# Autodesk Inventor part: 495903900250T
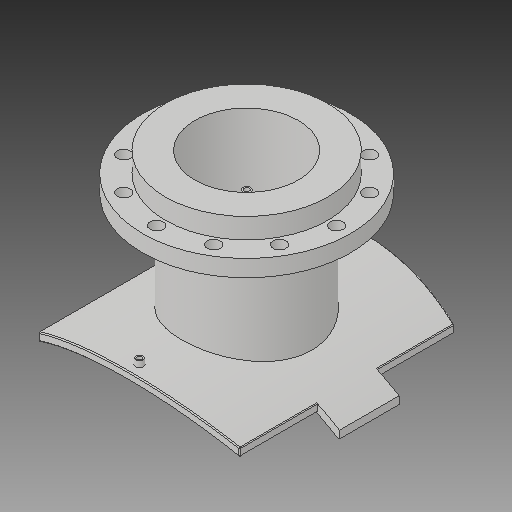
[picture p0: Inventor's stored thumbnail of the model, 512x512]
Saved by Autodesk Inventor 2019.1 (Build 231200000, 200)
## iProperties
Created: 2017-10
Part Number: 495903900250T
Material: Generic
Description: PLASSON FLANGED BRANCH SADDLE 900X250
Document SubType Name: Modeling
Designer: KIM
Mass: 2339.99 g
Surface Area: 3251.55 cm^2
Volume: 2339.99 cm^3
Density: 1 g/cm^3
Appearance: Default
Author: KIM
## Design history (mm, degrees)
derived "495904_495903.ipt"
feature "Solid1::495904_495903.ipt"
feature "Solid2::495904_495903.ipt"
tag "TaggingFeature1"
body "Solid1"
other parameters: "d1" = 15, "d2" = 396, "d4" = 0, "d6" = 117.5, "d7" = 0, "d12" = 475.6, "d13" = 14, "d14" = 211.5, "d16" = 5 deg, "d18" = 4, "d19" = 14, "d20" = 0, "d21" = 3, "d22" = 0, "d36" = 211.5, "d38" = 0, "d39" = 2, "d41" = 204, "d46" = 256, "d47" = 16, "d48" = 10.4, "d49" = 192.5, "d51" = 918, "d53" = 0, "d54" = 26, "d55" = 177.5, "d57" = 0, "d59" = 360 deg, "d61" = 33, "d63" = 0, "d66" = 275, "d67" = 15, "d68" = 137.5, "d70" = 0, "d71" = 2, "H_" = 275, "x_" = 15, "D_" = 16, "DN_" = 204, "t_" = 33, "s_" = 26, "Dp_" = 355
